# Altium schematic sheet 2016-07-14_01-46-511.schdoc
size 232 x 167 mm; SheetNumber: 1; SheetTotal: 1
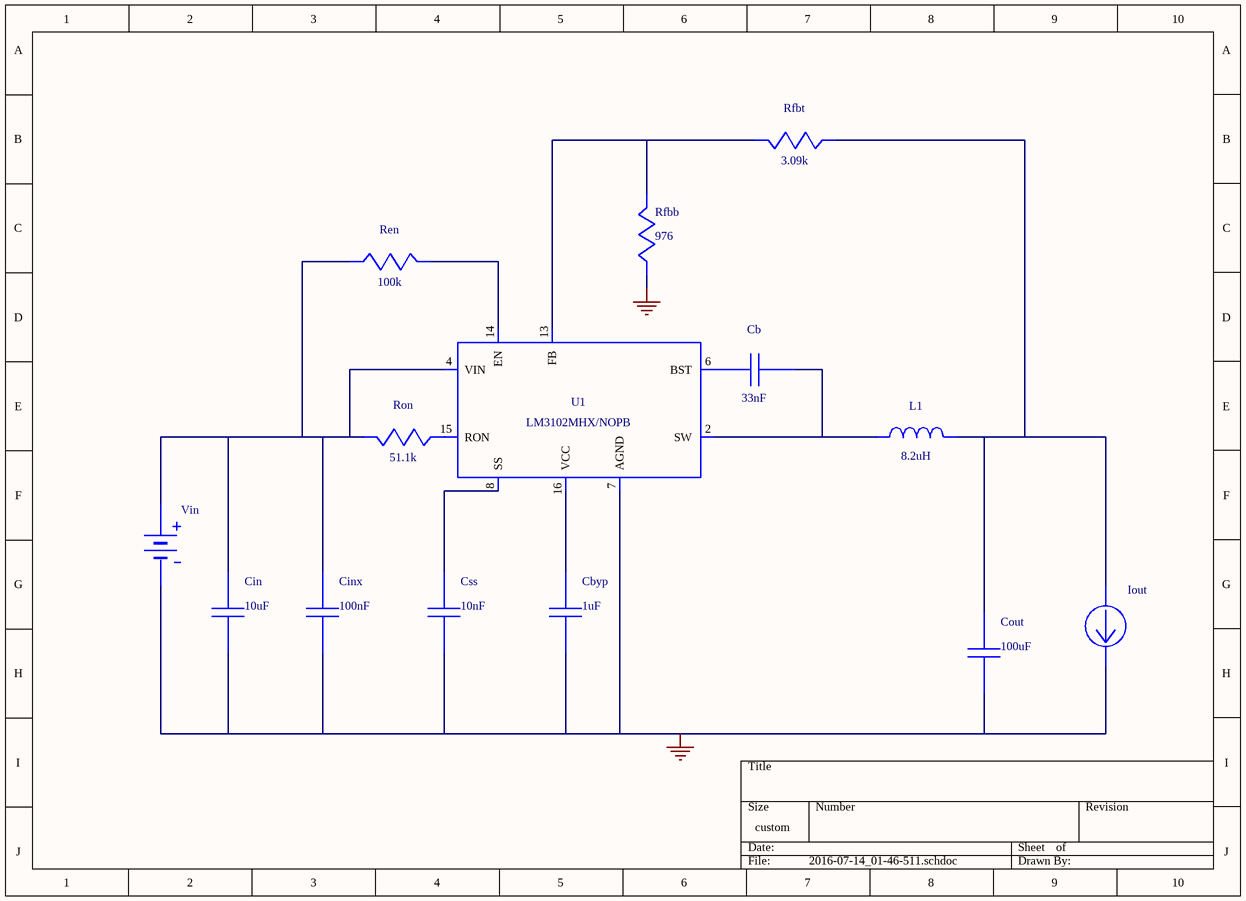
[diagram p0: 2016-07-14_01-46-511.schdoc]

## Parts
Cb  value 33nF  (hidden comment: GRM155R71E333KA88D)
Cbyp  value 1uF  (hidden comment: GRM188R61E105KA12D)
Cin  value 10uF  (hidden comment: GRM32ER7YA106KA12L)
Cinx  value 100nF  (hidden comment: C0805C104K5RACTU)
Cout  value 100uF  (hidden comment: GRM31CR60J107ME39L)
Css  value 10nF  (hidden comment: GRM155R71E103KA01D)
Iout  WB_CURRENT_LOAD  (value not drawn)
L1  value 8.2uH  (hidden comment: SRN8040-8R2Y)
Ren  value 100k  (hidden comment: CRCW0402100KFKED)
Rfbb  value 976  (hidden comment: CRCW0402976RFKED)
Rfbt  value 3.09k  (hidden comment: CRCW04023K09FKED)
Ron  value 51.1k  (hidden comment: CRCW040251K1FKED)
U1  LM3102MHX/NOPB
Vin  WB_BATTERY  (value not drawn)

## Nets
0: Cbyp.2 Cin.2 Cinx.2 Cout.2 Css.2 Iout.2(-) Rfbb.2 U1.1(NC) U1.7(AGND) U1.9(NC) U1.10(NC) U1.11(GND) U1.12(NC) U1.17(PGND) U1.18(PGND) U1.19(NC) U1.20(NC) U1.21(DAP) Vin.2(-)
NetCb_1: Cb.1 U1.6(BST)
NetCb_2: Cb.2 L1.1 U1.2(SW) U1.3(SW)
NetCbyp_1: Cbyp.1 U1.16(VCC)
NetCin_1: Cin.1 Cinx.1 Ren.2 Ron.1 U1.4(VIN) U1.5(VIN) Vin.1(+)
NetCout_1: Cout.1 Iout.1(+) L1.2 Rfbt.2
NetCss_1: Css.1 U1.8(SS)
NetRen_1: Ren.1 U1.14(EN)
NetRfbb_1: Rfbb.1 Rfbt.1 U1.13(FB)
NetRon_2: Ron.2 U1.15(RON)

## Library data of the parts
Cb = GRM155R71E333KA88D: GRM155R71E333KA8; Manufacturer Name: MuRata
Cbyp = GRM188R61E105KA12D: GRM188R61E105KA1; Manufacturer Name: MuRata
Cin = GRM32ER7YA106KA12L: GRM32ER7YA106KA1; Manufacturer Name: MuRata
Cinx = C0805C104K5RACTU: Manufacturer Name: Kemet
Cout = GRM31CR60J107ME39L: GRM31CR60J107ME3; Manufacturer Name: MuRata
Css = GRM155R71E103KA01D: GRM155R71E103KA0; Manufacturer Name: MuRata
L1 = SRN8040-8R2Y: Manufacturer Name: Bourns
Ren = CRCW0402100KFKED: Manufacturer Name: Vishay-Dale
Rfbb = CRCW0402976RFKED: Manufacturer Name: Vishay-Dale
Rfbt = CRCW04023K09FKED: Manufacturer Name: Vishay-Dale
Ron = CRCW040251K1FKED: Manufacturer Name: Vishay-Dale
U1 = LM3102MHX/NOPB: Manufacturer Name: Texas Instruments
